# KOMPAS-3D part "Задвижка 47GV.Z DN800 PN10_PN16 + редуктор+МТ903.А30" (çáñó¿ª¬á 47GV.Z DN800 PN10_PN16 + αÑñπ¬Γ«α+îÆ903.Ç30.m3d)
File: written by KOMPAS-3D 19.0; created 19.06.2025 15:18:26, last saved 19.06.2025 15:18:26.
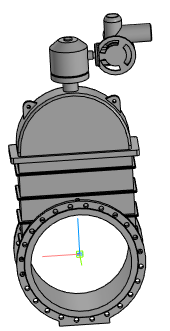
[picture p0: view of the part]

Document properties: Полное имя файла: Задвижка 47GV.Z DN800 PN10_PN16 + редуктор+МТ903.А30.a3d

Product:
- Part/product: Задвижка 47GV.Z DN800 PN10_PN16 + редуктор+МТ903.А30
    Масса: 2770.7

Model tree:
1. Операция без истории:1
